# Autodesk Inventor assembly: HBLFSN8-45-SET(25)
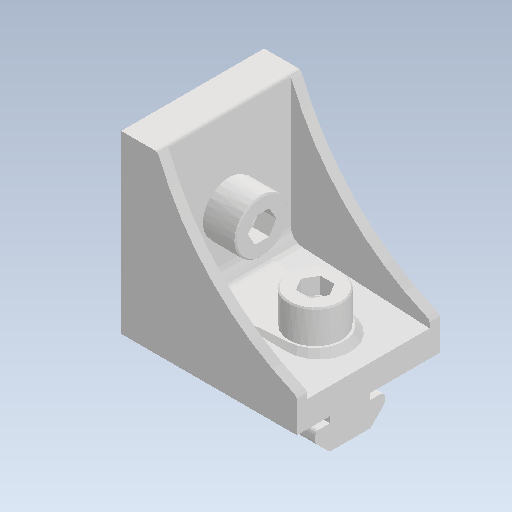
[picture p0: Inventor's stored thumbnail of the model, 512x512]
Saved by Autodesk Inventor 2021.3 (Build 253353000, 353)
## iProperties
Created: 2022-02
Part Number: HBLFSN8-45-SET(25)
Document SubType Name: Assembly
Designer: kengo
Author: kengo
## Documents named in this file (4)
- C:\Users\kengo\Documents\S2S_frame\SDC345\frame_misumi_ver12\HBLFSN8-45-SET(25).iam
- C:\Users\kengo\Documents\S2S_frame\SDC345\frame_misumi_ver12\HBLFSN8-45.ipt
- C:\Users\kengo\Documents\S2S_frame\SDC345\frame_misumi_ver12\HNTT8-8.ipt
- C:\Users\kengo\Documents\S2S_frame\SDC345\frame_misumi_ver12\CBM8-20.ipt
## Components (5 placed, 3 different names)
1. HBLFSN8-45
2. HNTT8-8
3. CBM8-20
4. HNTT8-8:1
5. CBM8-20:1
